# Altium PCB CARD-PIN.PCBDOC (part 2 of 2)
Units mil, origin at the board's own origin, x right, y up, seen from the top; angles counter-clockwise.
Board outline 5110 x 4320 mil, 2 copper layers (Top Layer, Bottom Layer); 210 components, 32 nets, 795 pads, 360 vias.
Unrouted connection lines stored in the file: 450.
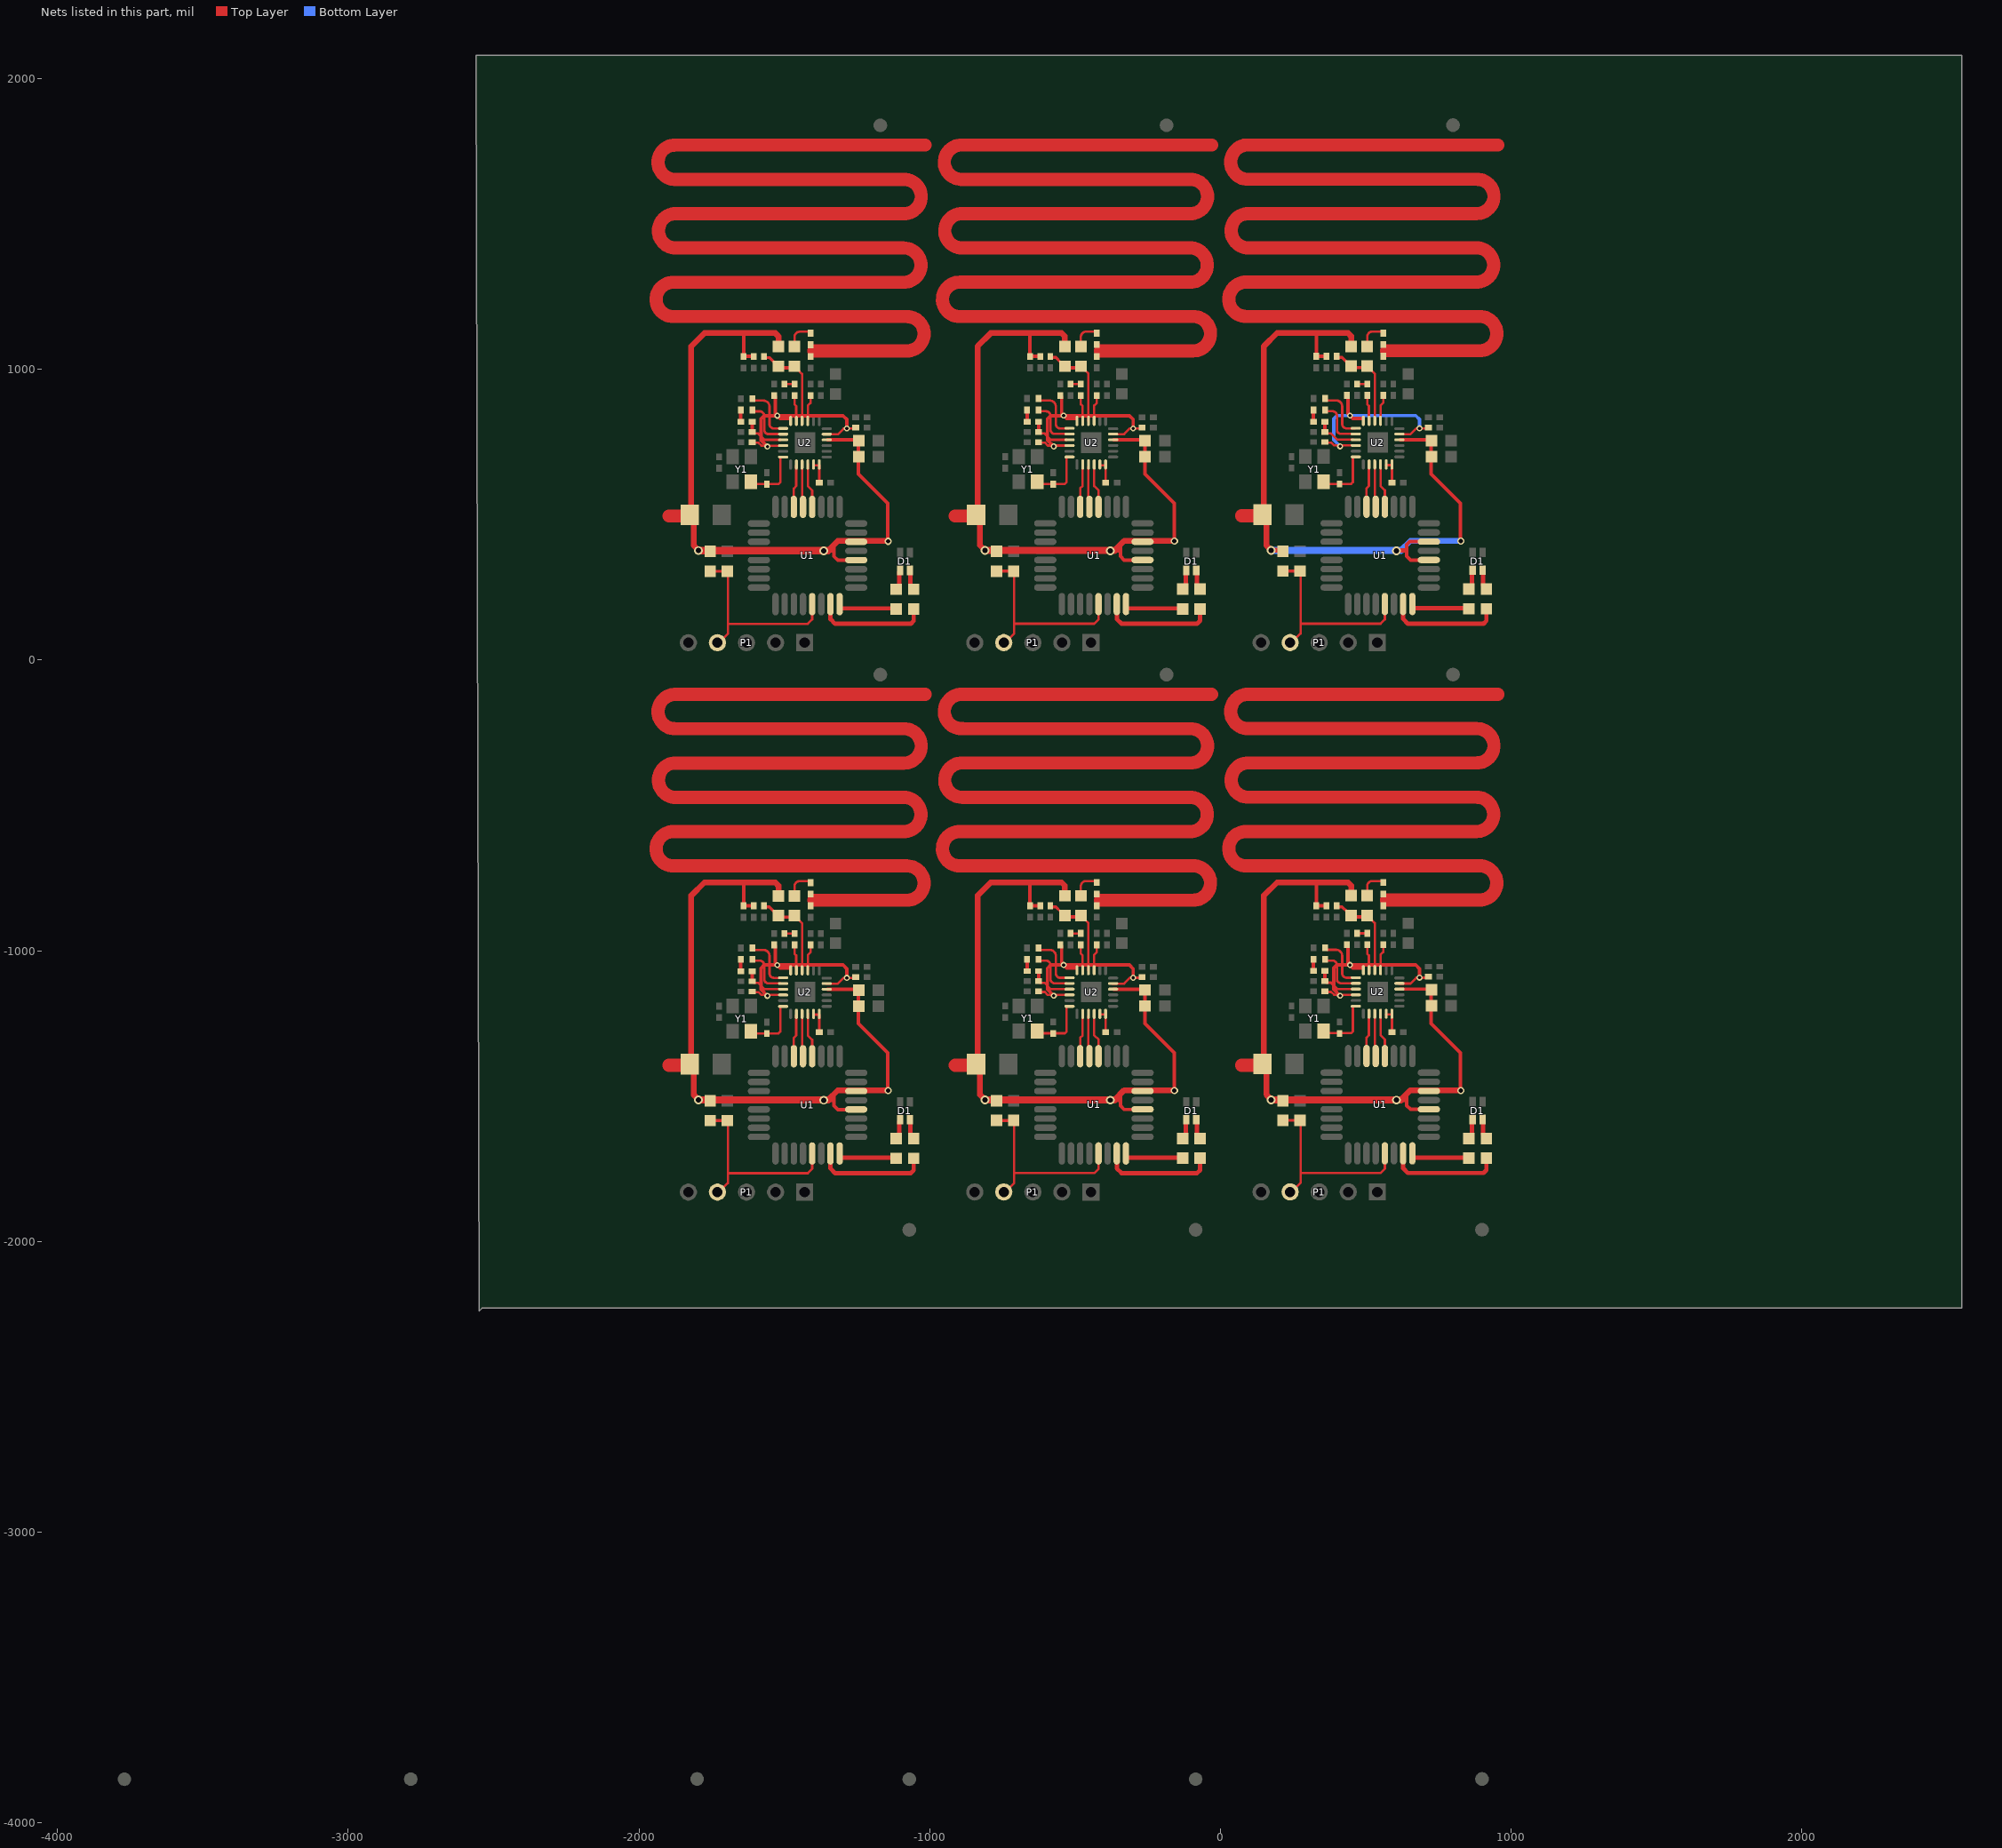
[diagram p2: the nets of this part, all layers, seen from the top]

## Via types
v1: diameter 28, hole 15, Top Layer to Bottom Layer, 240 vias
v2: diameter 20, hole 12, Top Layer to Bottom Layer, 36 vias
v3: diameter 20, hole 10, Top Layer to Bottom Layer, tented top, 30 vias
v4: diameter 22, hole 13, Top Layer to Bottom Layer, 18 vias
v5: diameter 21, hole 11, Top Layer to Bottom Layer, 18 vias
v6: diameter 30, hole 18, Top Layer to Bottom Layer, 12 vias
v7: diameter 25, hole 15, Top Layer to Bottom Layer, 6 vias

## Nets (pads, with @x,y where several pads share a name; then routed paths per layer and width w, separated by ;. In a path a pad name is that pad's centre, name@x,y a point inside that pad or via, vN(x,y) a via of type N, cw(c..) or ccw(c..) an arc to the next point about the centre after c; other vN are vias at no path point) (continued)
NetC9_2: C9.2 C12.2 | length 37793.3
  Top Layer w8: C12.2@-1411,-808.47 -1410,-808.27 C12.2@-1409.38,-808.14 ; C12.2@-1411,1081.53 -1410,1081.73 C12.2@-1409.38,1081.86 ; C12.2@-426,-808.24 -425,-808.03 C12.2@-424.38,-807.9 ; C12.2@-426,1081.76 -425,1081.97 C12.2@-424.38,1082.1 ; C12.2@559,-808 560,-807.79 C12.2@560.62,-807.66 ; C12.2@559,1082 560,1082.21 C12.2@560.62,1082.34
  Top Layer w13: C9.2@-1409.38,-845.45 C12.2@-1409.38,-808.14 ; C9.2@-1409.38,1044.55 C12.2@-1409.38,1081.86 ; C12.2@-1407.73,-805.46 C12.2@-1407.33,-802.49 ; C12.2@-1407.73,1084.54 C12.2@-1407.33,1087.51 ; C9.2@-424.38,-845.22 C12.2@-424.38,-807.9 ; C9.2@-424.38,1044.78 C12.2@-424.38,1082.1 ; C12.2@-422.73,-805.22 C12.2@-422.33,-802.25 ; C12.2@-422.73,1084.78 C12.2@-422.33,1087.75 ; C9.2@560.62,-844.98 C12.2@560.62,-807.66 ; C9.2@560.62,1045.02 C12.2@560.62,1082.34 ; C12.2@562.27,-804.99 C12.2@562.67,-802.02 ; C12.2@562.27,1085.01 C12.2@562.67,1087.98
  Top Layer w45.28: -1879.49,-708.49 -1080.51,-708.49 cw(c-1078.03,-767.49) -1081,-826.47 -1398,-826.47 ; -1879.49,-708.46 cw(c-1881.97,-649.45) -1879,-590.47 -1090.41,-590.47 ; -1879.49,1181.51 -1080.51,1181.51 cw(c-1078.03,1122.51) -1081,1063.53 -1398,1063.53 ; -1879.49,1181.54 cw(c-1881.97,1240.55) -1879,1299.53 -1090.41,1299.53 ; -1876,-236.52 -1090.52,-236.52 cw(c-1088.04,-295.53) -1091.01,-354.51 -1871,-354.51 ccw(c-1873.97,-413.49) -1871.49,-472.49 -1091.51,-472.49 cw(c-1089.03,-531.49) -1092,-590.47 ; -1876,-118.54 -1015,-118.54 ; -1876,1653.48 -1090.52,1653.48 cw(c-1088.04,1594.47) -1091.01,1535.49 -1871,1535.49 ccw(c-1873.97,1476.51) -1871.49,1417.51 -1091.51,1417.51 cw(c-1089.03,1358.51) -1092,1299.53 ; -1876,1771.46 -1015,1771.46 ; -1873,-236.47 cw(c-1875.48,-177.47) -1872.51,-118.49 ; -1873,1653.53 cw(c-1875.48,1712.53) -1872.51,1771.51 ; -894.49,-708.25 -95.51,-708.25 cw(c-93.03,-767.26) -96,-826.24 -413,-826.24 ; -894.49,-708.22 cw(c-896.97,-649.22) -894,-590.24 -105.41,-590.24 ; -894.49,1181.75 -95.51,1181.75 cw(c-93.03,1122.74) -96,1063.76 -413,1063.76 ; -894.49,1181.78 cw(c-896.97,1240.78) -894,1299.76 -105.41,1299.76 ; -891,-236.29 -105.52,-236.29 cw(c-103.04,-295.29) -106.01,-354.27 -886,-354.27 ccw(c-888.97,-413.25) -886.49,-472.25 -106.51,-472.25 cw(c-104.03,-531.26) -107,-590.24 ; -891,-118.3 -30,-118.3 ; -891,1653.71 -105.52,1653.71 cw(c-103.04,1594.71) -106.01,1535.73 -886,1535.73 ccw(c-888.97,1476.75) -886.49,1417.75 -106.51,1417.75 cw(c-104.03,1358.74) -107,1299.76 ; -891,1771.7 -30,1771.7 ; -888,-236.24 cw(c-890.48,-177.23) -887.51,-118.25 ; -888,1653.76 cw(c-890.48,1712.77) -887.51,1771.75 ; 94,-236.05 879.48,-236.05 cw(c881.96,-295.05) 878.99,-354.03 99,-354.03 ccw(c96.03,-413.01) 98.51,-472.02 878.49,-472.02 cw(c880.97,-531.02) 878,-590 ; 94,-118.07 955,-118.07 ; 94,1653.95 879.48,1653.95 cw(c881.96,1594.95) 878.99,1535.97 99,1535.97 ccw(c96.03,1476.99) 98.51,1417.98 878.49,1417.98 cw(c880.97,1358.98) 878,1300 ; 94,1771.93 955,1771.93 ; 97,-236 cw(c94.52,-177) 97.49,-118.02 ; 97,1654 cw(c94.52,1713) 97.49,1771.98 ; 572,-826 889,-826 ccw(c891.97,-767.02) 889.49,-708.02 90.51,-708.02 cw(c88.03,-648.98) 91,-590 879.59,-590 ; 572,1064 889,1064 ccw(c891.97,1122.98) 889.49,1181.98 90.51,1181.98 cw(c88.03,1241.02) 91,1300 879.59,1300
NetC10_1: C10.1 U2.3 | length 531.3
  Top Layer w8: U2.3@-1419.16,-1064.91 -1419.16,-1014.63 -1410,-1005.47 C10.1@-1410,-980.16 ; U2.3@-1419.16,825.09 -1419.16,875.37 -1410,884.53 C10.1@-1410,909.84 ; U2.3@-434.16,-1064.68 -434.16,-1014.39 -425,-1005.24 C10.1@-425,-979.92 ; U2.3@-434.16,825.32 -434.16,875.61 -425,884.76 C10.1@-425,910.08 ; U2.3@550.84,-1064.44 550.84,-1014.16 560,-1005 C10.1@560,-979.68 ; U2.3@550.84,825.56 550.84,875.84 560,885 C10.1@560,910.32
NetC11_2: C11.2 L2.1 L3.1 U2.4 | length 1708.5
  Top Layer w8: L2.1@-1455,-889.47 -1439,-905.47 U2.4@-1439,-1061.47 ; L2.1@-1455,1000.53 -1439,984.53 U2.4@-1439,828.53 ; U2.4@-1439,-1067.47 -1438.99,-1064.91 U2.4@-1439,-1066.47 ; U2.4@-1439,822.53 -1438.99,825.09 U2.4@-1439,823.53 ; L2.1@-470,-889.24 -454,-905.24 U2.4@-454,-1061.24 ; L2.1@-470,1000.76 -454,984.76 U2.4@-454,828.76 ; U2.4@-454,-1067.24 -453.99,-1064.68 U2.4@-454,-1066.24 ; U2.4@-454,822.76 -453.99,825.32 U2.4@-454,823.76 ; L2.1@515,-889 531,-905 U2.4@531,-1061 ; L2.1@515,1001 531,985 U2.4@531,829 ; U2.4@531,-1067 531.01,-1064.44 U2.4@531,-1066 ; U2.4@531,823 531.01,825.56 U2.4@531,824
  Top Layer w10: C11.2@-1567,-849.47 -1551,-849.47 L3.1@-1533.31,-867.16 ; C11.2@-1567,1040.53 -1551,1040.53 L3.1@-1533.31,1022.84 ; C11.2@-582,-849.24 -566,-849.24 L3.1@-548.31,-866.92 ; C11.2@-582,1040.76 -566,1040.76 L3.1@-548.31,1023.08 ; C11.2@403,-849 419,-849 L3.1@436.69,-866.69 ; C11.2@403,1041 419,1041 L3.1@436.69,1023.31
  Top Layer w12: L3.1@-1529,-884.47 L2.1@-1468,-884.47 ; L3.1@-1529,1005.53 L2.1@-1468,1005.53 ; L3.1@-544,-884.24 L2.1@-483,-884.24 ; L3.1@-544,1005.76 L2.1@-483,1005.76 ; L3.1@441,-884 L2.1@502,-884 ; L3.1@441,1006 L2.1@502,1006
NetC12_1: C12.1 L2.2 | length 560.2
  Top Layer w8: L2.2@-1465,-814.47 -1465,-778.54 cw(c-1447.93,-778.54) -1460,-766.47 ; L2.2@-1465,1075.53 -1465,1111.46 cw(c-1447.93,1111.46) -1460,1123.53 ; -1459,-765.47 cw(c-1447.51,-776.96) -1447.51,-760.71 C12.1@-1416.24,-760.71 ; -1459,1124.53 cw(c-1447.51,1113.04) -1447.51,1129.28 C12.1@-1416.24,1129.28 ; L2.2@-480,-814.24 -480,-778.31 cw(c-462.93,-778.31) -475,-766.24 ; L2.2@-480,1075.76 -480,1111.69 cw(c-462.93,1111.69) -475,1123.76 ; -474,-765.24 cw(c-462.51,-776.72) -462.51,-760.48 C12.1@-431.24,-760.48 ; -474,1124.76 cw(c-462.51,1113.28) -462.51,1129.52 C12.1@-431.24,1129.52 ; L2.2@505,-814 505,-778.07 cw(c522.07,-778.07) 510,-766 ; L2.2@505,1076 505,1111.93 cw(c522.07,1111.93) 510,1124 ; 511,-765 cw(c522.49,-776.49) 522.49,-760.24 C12.1@553.76,-760.24 ; 511,1125 cw(c522.49,1113.51) 522.49,1129.76 C12.1@553.76,1129.76
NetC13_1: C13.1 U2.17 U2.18 | length 438.1
  Top Layer w8: U2.17@-1399.47,-1220.03 -1379.79,-1220.03 C13.1@-1379.79,-1273.37 ; U2.17@-1399.47,669.97 -1379.79,669.97 C13.1@-1379.79,616.63 ; U2.17@-414.47,-1219.8 -394.79,-1219.8 C13.1@-394.79,-1273.13 ; U2.17@-414.47,670.2 -394.79,670.2 C13.1@-394.79,616.87 ; U2.17@570.53,-1219.56 590.21,-1219.56 C13.1@590.21,-1272.9 ; U2.17@570.53,670.44 590.21,670.44 C13.1@590.21,617.1
NetC16_2: C16.2 R2.2 | length 172.2
  Top Layer w8: C16.2@-1494.69,-940.79 R2.2@-1466,-940.79 ; C16.2@-1494.69,949.21 R2.2@-1466,949.21 ; C16.2@-509.69,-940.55 R2.2@-481,-940.55 ; C16.2@-509.69,949.45 R2.2@-481,949.45 ; C16.2@475.31,-940.31 R2.2@504,-940.31 ; C16.2@475.31,949.69 R2.2@504,949.69
NetC19_2: C19.2 R4.2 U2.9 | length 777
  Top Layer w8: C19.2@-1610,-1105.47 -1605,-1110.47 -1590,-1110.47 -1568,-1132.47 U2.9@-1514,-1132.47 ; C19.2@-1610,784.53 -1605,779.53 -1590,779.53 -1568,757.53 U2.9@-1514,757.53 ; C19.2@-625,-1105.24 -620,-1110.24 -605,-1110.24 -583,-1132.24 U2.9@-529,-1132.24 ; C19.2@-625,784.76 -620,779.76 -605,779.76 -583,757.76 U2.9@-529,757.76 ; C19.2@360,-1105 365,-1110 380,-1110 402,-1132 U2.9@456,-1132 ; C19.2@360,785 365,780 380,780 402,758 U2.9@456,758
  Top Layer w12: C19.2@-1610,-1097.79 R4.2@-1610,-1075.47 ; C19.2@-1610,792.21 R4.2@-1610,814.53 ; C19.2@-625,-1097.55 R4.2@-625,-1075.24 ; C19.2@-625,792.45 R4.2@-625,814.76 ; C19.2@360,-1097.31 R4.2@360,-1075 ; C19.2@360,792.69 R4.2@360,815
NetC20_2: C20.2 R4.1 | length 258
  Top Layer w12: R4.1@-1650,-1073.47 C20.2@-1650,-1030.47 ; R4.1@-1650,816.53 C20.2@-1650,859.53 ; R4.1@-665,-1073.24 C20.2@-665,-1030.24 ; R4.1@-665,816.76 C20.2@-665,859.76 ; R4.1@320,-1073 C20.2@320,-1030 ; R4.1@320,817 C20.2@320,860
NetC21_2: C21.2 U2.12 Y1.3 | length 1081.6
  Top Layer w8: Y1.3@-1605,-1284.47 -1520,-1284.47 -1514,-1278.47 U2.12@-1514,-1191.68 ; Y1.3@-1605,605.53 -1520,605.53 -1514,611.53 U2.12@-1514,698.32 ; Y1.3@-620,-1284.24 -535,-1284.24 -529,-1278.24 U2.12@-529,-1191.45 ; Y1.3@-620,605.76 -535,605.76 -529,611.76 U2.12@-529,698.55 ; Y1.3@365,-1284 450,-1284 456,-1278 U2.12@456,-1191.21 ; Y1.3@365,606 450,606 456,612 U2.12@456,698.79
NetD1_1: D1.1 R3.2 | length 312.1
  Top Layer w15: R3.2@-1103.99,-1637.46 D1.1@-1104,-1587.47 ; R3.2@-1103.99,252.54 D1.1@-1104,302.53 ; D1.1@-1103,-1579.47 D1.1@-1102.92,-1581.51 ; D1.1@-1103,310.53 D1.1@-1102.92,308.49 ; R3.2@-118.98,-1637.22 D1.1@-119,-1587.24 ; R3.2@-118.98,252.78 D1.1@-119,302.76 ; D1.1@-118,-1579.24 D1.1@-117.92,-1581.27 ; D1.1@-118,310.76 D1.1@-117.92,308.73 ; R3.2@866.02,-1636.99 D1.1@866,-1587 ; R3.2@866.02,253.01 D1.1@866,303 ; D1.1@867,-1579 D1.1@867.08,-1581.04 ; D1.1@867,311 D1.1@867.08,308.96
NetD1_2: D1.2 R5.2 | length 299.9
  Top Layer w15: R5.2@-1065.98,-1632.46 D1.2@-1066,-1582.47 ; R5.2@-1065.98,257.54 D1.2@-1066,307.53 ; R5.2@-80.98,-1632.22 D1.2@-81,-1582.24 ; R5.2@-80.98,257.78 D1.2@-81,307.76 ; R5.2@904.02,-1631.99 D1.2@904,-1582 ; R5.2@904.02,258.01 D1.2@904,308
NetL4_1: L4.1 U2.7 | length 1059.3
  Top Layer w8: L4.1@-1602,-997.47 -1571,-997.47 ; L4.1@-1602,892.53 -1571,892.53 ; -1572,-997.47 cw(c-1572,-1018.47) -1551,-1018.47 ; -1572,892.53 cw(c-1572,871.53) -1551,871.53 ; -1551,-1017.47 -1551,-1078.47 ccw(c-1536,-1078.47) -1536,-1093.47 U2.7@-1508,-1093.47 ; -1551,872.53 -1551,811.53 ccw(c-1536,811.53) -1536,796.53 U2.7@-1508,796.53 ; L4.1@-617,-997.24 -586,-997.24 ; L4.1@-617,892.76 -586,892.76 ; -587,-997.24 cw(c-587,-1018.24) -566,-1018.24 ; -587,892.76 cw(c-587,871.76) -566,871.76 ; -566,-1017.24 -566,-1078.24 ccw(c-551,-1078.24) -551,-1093.24 U2.7@-523,-1093.24 ; -566,872.76 -566,811.76 ccw(c-551,811.76) -551,796.76 U2.7@-523,796.76 ; L4.1@368,-997 399,-997 ; L4.1@368,893 399,893 ; 398,-997 cw(c398,-1018) 419,-1018 ; 398,893 cw(c398,872) 419,872 ; 419,-1017 419,-1078 ccw(c434,-1078) 434,-1093 U2.7@462,-1093 ; 419,873 419,812 ccw(c434,812) 434,797 U2.7@462,797
NetL4_2: L4.2 U2.8 | length 966.7
  Top Layer w8: L4.2@-1609,-1034.47 -1585,-1034.47 cw(c-1585,-1050.47) -1569,-1050.47 -1569,-1098.47 ccw(c-1555,-1098.47) -1555,-1112.47 ; L4.2@-1609,855.53 -1585,855.53 cw(c-1585,839.53) -1569,839.53 -1569,791.53 ccw(c-1555,791.53) -1555,777.53 ; -1556,-1112.47 U2.8@-1514,-1112.47 ; -1556,777.53 U2.8@-1514,777.53 ; L4.2@-624,-1034.24 -600,-1034.24 cw(c-600,-1050.24) -584,-1050.24 -584,-1098.24 ccw(c-570,-1098.24) -570,-1112.24 ; L4.2@-624,855.76 -600,855.76 cw(c-600,839.76) -584,839.76 -584,791.76 ccw(c-570,791.76) -570,777.76 ; -571,-1112.24 U2.8@-529,-1112.24 ; -571,777.76 U2.8@-529,777.76 ; L4.2@361,-1034 385,-1034 cw(c385,-1050) 401,-1050 401,-1098 ccw(c415,-1098) 415,-1112 ; L4.2@361,856 385,856 cw(c385,840) 401,840 401,792 ccw(c415,792) 415,778 ; 414,-1112 U2.8@456,-1112 ; 414,778 U2.8@456,778
NetR2_1: R2.1 U2.5 | length 470.9
  Top Layer w8: R2.1@-1465,-983.47 -1465,-1010.47 -1459,-1016.47 U2.5@-1459,-1059.47 ; R2.1@-1465,906.53 -1465,879.53 -1459,873.53 U2.5@-1459,830.53 ; R2.1@-480,-983.24 -480,-1010.24 -474,-1016.24 U2.5@-474,-1059.24 ; R2.1@-480,906.76 -480,879.76 -474,873.76 U2.5@-474,830.76 ; R2.1@505,-983 505,-1010 511,-1016 U2.5@511,-1059 ; R2.1@505,907 505,880 511,874 U2.5@511,831
NetR3_1: R3.1 U1.32 | length 1171.9
  Top Layer w15: U1.32@-1309.99,-1697.8 U1.32@-1310,-1695.47 ; U1.32@-1309.99,192.2 U1.32@-1310,194.53 ; U1.32@-1306,-1712.47 R3.1@-1113,-1712.47 ; U1.32@-1306,177.53 R3.1@-1113,177.53 ; U1.32@-324.99,-1697.56 U1.32@-325,-1695.24 ; U1.32@-324.99,192.44 U1.32@-325,194.76 ; U1.32@-321,-1712.24 R3.1@-128,-1712.24 ; U1.32@-321,177.76 R3.1@-128,177.76 ; U1.32@660.01,-1697.32 U1.32@660,-1695 ; U1.32@660.01,192.68 U1.32@660,195 ; U1.32@664,-1712 R3.1@857,-1712 ; U1.32@664,178 R3.1@857,178
NetR5_1: R5.1 U1.31 | length 2379.4
  Top Layer w15: U1.31@-1341,-1693.47 -1341.02,-1697.8 -1341.01,-1749.47 -1325,-1765.47 -1064.92,-1765.39 -1055,-1755.47 R5.1@-1055,-1714.47 R5.1@-1053,-1712.47 ; U1.31@-1341,196.53 -1341.02,192.2 -1341.01,140.53 -1325,124.53 -1064.92,124.61 -1055,134.53 R5.1@-1055,175.53 R5.1@-1053,177.53 ; U1.31@-356,-1693.24 -356.02,-1697.56 -356.01,-1749.23 -340,-1765.24 -79.92,-1765.16 -70,-1755.23 -70.01,-1714.25 R5.1@-68,-1712.24 ; U1.31@-356,196.76 -356.02,192.44 -356.01,140.77 -340,124.76 -79.92,124.84 -70,134.77 -70.01,175.75 R5.1@-68,177.76 ; U1.31@629,-1693 628.98,-1697.32 628.99,-1749 645,-1765 905.08,-1764.92 915,-1755 R5.1@915,-1714 R5.1@917,-1712 ; U1.31@629,197 628.98,192.68 628.99,141 645,125 905.08,125.08 915,135 R5.1@915,176 R5.1@917,178
RST: C4.1 P1.4 R1.1 U1.29 | length 3882.7
  Top Layer w8: P1.4@-1730,-1835.47 -1694,-1799.47 C4.1@-1694,-1584.47 ; P1.4@-1730,54.53 -1694,90.53 C4.1@-1694,305.53 ; -1692,-1765.47 -1419,-1765.47 -1404,-1750.47 U1.29@-1404,-1722.47 ; -1692,124.53 -1419,124.53 -1404,139.53 U1.29@-1404,167.53 ; P1.4@-745,-1835.24 -709,-1799.24 C4.1@-709,-1584.24 ; P1.4@-745,54.76 -709,90.76 C4.1@-709,305.76 ; -707,-1765.24 -434,-1765.24 -419,-1750.24 U1.29@-419,-1722.24 ; -707,124.76 -434,124.76 -419,139.76 U1.29@-419,167.76 ; P1.4@240,-1835 276,-1799 C4.1@276,-1584 ; P1.4@240,55 276,91 C4.1@276,306 ; 278,-1765 551,-1765 566,-1750 U1.29@566,-1722 ; 278,125 551,125 566,140 U1.29@566,168
  Top Layer w10: R1.1@-1755,-1584.47 C4.1@-1696,-1584.47 ; R1.1@-1755,305.53 C4.1@-1696,305.53 ; R1.1@-770,-1584.24 C4.1@-711,-1584.24 ; R1.1@-770,305.76 C4.1@-711,305.76 ; R1.1@215,-1584 C4.1@274,-1584 ; R1.1@215,306 C4.1@274,306
SCK: U1.13 U2.15 | length 690
  Top Layer w8: U1.13@-1439,-1341.47 U2.15@-1439,-1226.47 ; U1.13@-1439,548.53 U2.15@-1439,663.53 ; U1.13@-454,-1341.24 U2.15@-454,-1226.24 ; U1.13@-454,548.76 U2.15@-454,663.76 ; U1.13@531,-1341 U2.15@531,-1226 ; U1.13@531,549 U2.15@531,664
SCS: U1.14 U2.14 | length 870.6
  Top Layer w8: U1.14@-1467.24,-1363.15 -1467.24,-1299.72 -1459,-1291.47 U2.14@-1459,-1221.47 ; U1.14@-1467.24,526.85 -1467.24,590.28 -1459,598.53 U2.14@-1459,668.53 ; U1.14@-482.24,-1362.91 -482.24,-1299.48 -474,-1291.24 U2.14@-474,-1221.24 ; U1.14@-482.24,527.09 -482.24,590.52 -474,598.76 U2.14@-474,668.76 ; U1.14@502.76,-1362.68 502.76,-1299.24 511,-1291 U2.14@511,-1221 ; U1.14@502.76,527.32 502.76,590.76 511,599 U2.14@511,669
SDIO: U1.12 U2.16 | length 850.6
  Top Layer w8: U2.16@-1419,-1220.03 U2.16@-1419,-1219.47 ; U2.16@-1419,-1216.47 -1419,-1291.47 -1404,-1306.47 U1.12@-1404,-1351.47 ; U2.16@-1419,669.97 U2.16@-1419,670.53 ; U2.16@-1419,673.53 -1419,598.53 -1404,583.53 U1.12@-1404,538.53 ; U2.16@-434,-1219.8 U2.16@-434,-1219.24 ; U2.16@-434,-1216.24 -434,-1291.24 -419,-1306.24 U1.12@-419,-1351.24 ; U2.16@-434,670.2 U2.16@-434,670.76 ; U2.16@-434,673.76 -434,598.76 -419,583.76 U1.12@-419,538.76 ; U2.16@551,-1219.56 U2.16@551,-1219 ; U2.16@551,-1216 551,-1291 566,-1306 U1.12@566,-1351 ; U2.16@551,670.44 U2.16@551,671 ; U2.16@551,674 551,599 566,584 U1.12@566,539
VCC: C1.2 C5.1 C6.1 C14.1 C15.1 L3.2 R1.2 U1.4 U1.6 U2.22 | length 15657.4
  Top Layer w12: C15.1@-1641,-846.47 -1640,-845.47 -1640,-765.47 ; C15.1@-1641,-845.47 C14.1@-1603,-845.47 ; C15.1@-1641,1043.53 -1640,1044.53 -1640,1124.53 ; C15.1@-1641,1044.53 C14.1@-1603,1044.53 ; U2.22@-1351.44,-1132.63 C6.1@-1244,-1132.63 ; U2.22@-1351.44,757.37 C6.1@-1244,757.37 ; U1.4@-1272,-1546.47 -1316,-1546.47 -1329,-1533.47 -1329,-1493.47 -1318,-1482.47 U1.6@-1271,-1482.47 ; U1.4@-1272,343.53 -1316,343.53 -1329,356.53 -1329,396.53 -1318,407.53 U1.6@-1271,407.53 ; C6.1@-1245,-1135.47 -1245,-1250.47 -1144,-1351.47 v7@-1144,-1480.47 ; C6.1@-1245,754.53 -1245,639.53 -1144,538.53 v7@-1144,409.53 ; C15.1@-656,-846.24 -655,-845.24 -655,-765.24 ; C15.1@-656,-845.24 C14.1@-618,-845.24 ; C15.1@-656,1043.76 -655,1044.76 -655,1124.76 ; C15.1@-656,1044.76 C14.1@-618,1044.76 ; U2.22@-366.44,-1132.39 C6.1@-259,-1132.39 ; U2.22@-366.44,757.61 C6.1@-259,757.61 ; U1.4@-287,-1546.24 -331,-1546.24 -344,-1533.24 -344,-1493.24 -333,-1482.24 U1.6@-286,-1482.24 ; U1.4@-287,343.76 -331,343.76 -344,356.76 -344,396.76 -333,407.76 U1.6@-286,407.76 ; C6.1@-260,-1135.24 -260,-1250.24 -159,-1351.24 v7@-159,-1480.24 ; C6.1@-260,754.76 -260,639.76 -159,538.76 v7@-159,409.76 ; C15.1@329,-846 330,-845 330,-765 ; C15.1@329,-845 C14.1@367,-845 ; C15.1@329,1044 330,1045 330,1125 ; C15.1@329,1045 C14.1@367,1045 ; U2.22@618.56,-1132.16 C6.1@726,-1132.16 ; U2.22@618.56,757.84 C6.1@726,757.84 ; U1.4@698,-1546 654,-1546 641,-1533 641,-1493 652,-1482 U1.6@699,-1482 ; U1.4@698,344 654,344 641,357 641,397 652,408 U1.6@699,408 ; C6.1@725,-1135 725,-1250 826,-1351 v7@826,-1480 ; C6.1@725,755 725,640 826,539 v7@826,410
  Top Layer w15: v6@-1363,-1513.47 -1332,-1513.47 ; v6@-1363,376.53 -1332,376.53 ; v6@-378,-1513.24 -347,-1513.24 ; v6@-378,376.76 -347,376.76 ; v6@607,-1513 638,-1513 ; v6@607,377 638,377
  Top Layer w16: v6@-1795,-1512.47 R1.2@-1759,-1512.47 ; v6@-1795,377.53 R1.2@-1759,377.53 ; v6@-810,-1512.24 R1.2@-774,-1512.24 ; v6@-810,377.76 R1.2@-774,377.76 ; v6@175,-1512 R1.2@211,-1512 ; v6@175,378 R1.2@211,378
  Top Layer w20: C1.2@-1820,-1380.47 -1820,-810.47 -1775,-765.47 -1531,-765.47 -1520,-776.47 L3.2@-1520,-811.47 ; C1.2@-1820,509.53 -1820,1079.53 -1775,1124.53 -1531,1124.53 -1520,1113.53 L3.2@-1520,1078.53 ; C1.2@-1812,-1396.47 -1812,-1495.47 v6@-1795,-1512.47 ; C1.2@-1812,493.53 -1812,394.53 v6@-1795,377.53 ; -1349,-1513.47 -1316,-1480.47 v7@-1143,-1480.47 ; -1349,376.53 -1316,409.53 v7@-1143,409.53 ; C1.2@-835,-1380.24 -835,-810.24 -790,-765.24 -546,-765.24 -535,-776.24 L3.2@-535,-811.24 ; C1.2@-835,509.76 -835,1079.76 -790,1124.76 -546,1124.76 -535,1113.76 L3.2@-535,1078.76 ; C1.2@-827,-1396.24 -827,-1495.24 v6@-810,-1512.24 ; C1.2@-827,493.76 -827,394.76 v6@-810,377.76 ; -364,-1513.24 -331,-1480.24 v7@-158,-1480.24 ; -364,376.76 -331,409.76 v7@-158,409.76 ; C1.2@150,-1380 150,-810 195,-765 439,-765 450,-776 L3.2@450,-811 ; C1.2@150,510 150,1080 195,1125 439,1125 450,1114 L3.2@450,1079 ; C1.2@158,-1396 158,-1495 v6@175,-1512 ; C1.2@158,494 158,395 v6@175,378 ; 621,-1513 654,-1480 v7@827,-1480
  Top Layer w25: v6@-1794,-1513.47 -1349,-1513.47 ; v6@-1794,376.53 -1349,376.53 ; v6@-809,-1513.24 -364,-1513.24 ; v6@-809,376.76 -364,376.76 ; v6@176,-1513 621,-1513
  Top Layer w45: -1897,-1394.47 C1.2@-1849,-1394.47 ; -1897,495.53 C1.2@-1849,495.53 ; -912,-1394.24 C1.2@-864,-1394.24 ; -912,495.76 C1.2@-864,495.76 ; 73,-1394 C1.2@121,-1394 ; 73,496 C1.2@121,496
  Bottom Layer w20: 621,377 654,410 v7@827,410
  Bottom Layer w25: v6@176,377 621,377
  other v6: -1364,-1514.47 -379,-1514.24 606,-1514 -1795,-1513.47 -810,-1513.24 175,-1513 -1364,375.53 -379,375.76 606,376 -1795,376.53 -810,376.76 175,377
  other v7: -1143,-1481.47 -158,-1481.24 827,-1481 -1143,408.53 -158,408.76 827,409
VDA: C3.1 C17.1 C18.2 U2.6 U2.10 U2.23 | length 4613
  Top Layer w8: C18.2@-1604,-1142.47 -1589,-1142.47 -1579,-1152.47 U2.10@-1499,-1152.47 ; C18.2@-1604,747.53 -1589,747.53 -1579,737.53 U2.10@-1499,737.53 ; U2.23@-1356,-1113.47 -1316,-1113.47 -1296,-1093.47 C3.1@-1260,-1093.47 ; U2.23@-1356,776.53 -1316,776.53 -1296,796.53 C3.1@-1260,796.53 ; C18.2@-619,-1142.24 -604,-1142.24 -594,-1152.24 U2.10@-514,-1152.24 ; C18.2@-619,747.76 -604,747.76 -594,737.76 U2.10@-514,737.76 ; U2.23@-371,-1113.24 -331,-1113.24 -311,-1093.24 C3.1@-275,-1093.24 ; U2.23@-371,776.76 -331,776.76 -311,796.76 C3.1@-275,796.76 ; C18.2@366,-1142 381,-1142 391,-1152 U2.10@471,-1152 ; C18.2@366,748 381,748 391,738 U2.10@471,738 ; U2.23@614,-1113 654,-1113 674,-1093 C3.1@710,-1093 ; U2.23@614,777 654,777 674,797 C3.1@710,797
  Top Layer w12: v5(-1558,-1155.47) -1580,-1133.47 -1580,-1060.47 -1569,-1049.47 -1298,-1049.47 -1285,-1062.47 v5(-1285,-1093.47) ; v5(-1558,734.53) -1580,756.53 -1580,829.53 -1569,840.53 -1298,840.53 -1285,827.53 v5(-1285,796.53) ; C17.1@-1531,-984.16 -1531,-1042.47 -1514,-1059.47 U2.6@-1481,-1059.47 ; C17.1@-1531,905.84 -1531,847.53 -1514,830.53 U2.6@-1481,830.53 ; v5(-573,-1155.24) -595,-1133.24 -595,-1060.24 -584,-1049.24 -313,-1049.24 -300,-1062.24 v5(-300,-1093.24) ; v5(-573,734.76) -595,756.76 -595,829.76 -584,840.76 -313,840.76 -300,827.76 v5(-300,796.76) ; C17.1@-546,-983.92 -546,-1042.24 -529,-1059.24 U2.6@-496,-1059.24 ; C17.1@-546,906.08 -546,847.76 -529,830.76 U2.6@-496,830.76 ; v5(412,-1155) 390,-1133 390,-1060 401,-1049 672,-1049 685,-1062 v5(685,-1093) ; C17.1@439,-983.68 439,-1042 456,-1059 U2.6@489,-1059 ; C17.1@439,906.32 439,848 456,831 U2.6@489,831
  Bottom Layer w12: v5(412,735) 390,757 390,830 401,841 672,841 685,828 v5(685,797)
  other v5: -1524,-1049.47 -539,-1049.24 446,-1049 -1524,840.53 -539,840.76 446,841
pads on no net: U1.2 U1.7 U1.8 U1.10 U1.11 U1.18 U1.19 U1.20 U1.22 U1.23 U1.24 U1.25 U1.26 U1.27 U1.28 U1.30 U2.21 Y1.2 Y1.4
copper on no net: | length 76094.6
  Top Layer w6: -3940,-3780.71 -3940,-3900.47 -985,-3900.47 -985,-3780.47 ; -2955,-3780.47 -2955,-3900.24 0,-3900.24 0,-3780.24 ; -1970,-3780.24 -1970,-3900 985,-3900 985,-3780 ; -1355,-1015.47 -1355,-920.47 -1360,-920.47 -1560,-920.47 -1560,-1010.47 -1560,-1015.47 -1070,-1015.47 ; -1355,874.53 -1355,969.53 -1360,969.53 -1560,969.53 -1560,879.53 -1560,874.53 -1070,874.53 ; -1075,-80.47 -1030,-80.47 -1030,-0.47 ; -1075,-80 -1075,-0.71 ; -1075,1809.53 -1030,1809.53 -1030,1889.53 -985,1889.53 ; -1075,1810 -1075,1889.29 -1970,1889.29 ; -985,-2010.47 -985,-1890.47 ; -370,-1015.24 -370,-920.24 -375,-920.24 -575,-920.24 -575,-1010.24 -575,-1015.24 -85,-1015.24 ; -370,874.76 -370,969.76 -375,969.76 -575,969.76 -575,879.76 -575,874.76 -85,874.76 ; -90,-80.24 -45,-80.24 -45,-0.24 ; -90,-79.76 -90,-0.47 ; -90,1809.76 -45,1809.76 -45,1889.76 0,1889.76 0,-0.24 ; -90,1810.24 -90,1889.53 -985,1889.53 ; 0,-2010.24 0,-1890.24 ; 615,-1015 615,-920 610,-920 410,-920 410,-1010 410,-1015 900,-1015 ; 895,-80 940,-80 940,0 985,0 985,-1890 ; 895,-79.53 895,-0.24 0,-0.24 ; -1970,-1890.71 -1075,-1890.71 -1970,-1890.71 ; -1970,-1890.71 -1970,-0.71 ; -1970,-1890.71 -1970,-0.71 ; -1970,-0.71 -1075,-0.71 ; -1970,-0.71 -1970,-1890.47 -1075,-1890.47 -1075,-1810.47 -1030,-1810.47 -1030,-1890.47 ; -1970,-0.71 -1075,-0.71 ; -1970,-0.71 -1970,1889.29 ; -1970,-0.71 -1970,1889.29 ; -1970,-0.71 -1075,-0.71 ; -1970,1889.29 -1970,-0.47 -1075,-0.47 -1075,79.53 -1030,79.53 -1030,-0.47 ; -1030,-1890.47 -985,-1890.47 ; -1030,-1890.47 -985,-1890.47 ; -1030,-1890.47 -985,-1890.47 ; -1030,-0.47 -985,-0.47 ; -1030,-0.47 -985,-0.47 ; -1030,-0.47 -985,-0.47 ; -1030,-0.47 -985,-0.47 ; -985,-1890.47 -90,-1890.47 -985,-1890.47 ; -985,-1890.47 -985,-0.47 ; -985,-1890.47 -985,-0.47 ; -985,-1890.47 -985,-0.47 ; -985,-0.47 -90,-0.47 ; -985,-0.47 -985,-1890.24 -90,-1890.24 -90,-1810.24 -45,-1810.24 -45,-1890.24 ; -985,-0.47 -985,1889.53 ; -985,-0.47 -90,-0.47 ; -985,-0.47 -985,1889.53 ; -985,-0.47 -985,1889.53 ; -985,-0.47 -90,-0.47 ; -985,1889.53 -985,-0.24 -90,-0.24 -90,79.76 -45,79.76 -45,-0.24 ; -45,-1890.24 0,-1890.24 ; -45,-1890.24 0,-1890.24 ; -45,-1890.24 0,-1890.24 ; -45,-0.24 0,-0.24 ; -45,-0.24 0,-0.24 ; -45,-0.24 0,-0.24 ; -45,-0.24 0,-0.24 ; 0,-1890.24 895,-1890.24 0,-1890.24 ; 0,-1890.24 0,-0.24 ; 0,-1890.24 0,-0.24 ; 0,-1890.24 0,-0.24 ; 0,-0.24 0,-1890 895,-1890 895,-1810 940,-1810 940,-1890 ; 940,-1890 985,-1890 ; 940,-1890 985,-1890 ; 940,-1890 985,-1890 ; -1250,-1015.47 -1030,-1015.47 -1030,-915.47 -1250,-915.47 -1250,-1015.47 ; -1250,874.53 -1250,974.53 -1030,974.53 -1030,874.53 -1250,874.53 ; -265,-1015.24 -45,-1015.24 -45,-915.24 -265,-915.24 -265,-1015.24 ; -265,874.76 -265,974.76 -45,974.76 -45,874.76 -265,874.76 ; 720,-1015 720,-915 940,-915 940,-1015 720,-1015

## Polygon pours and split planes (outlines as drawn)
GND on Top Layer "Bottom Layer-No Net" (solid, remove dead copper, pour order 1001): -490,210 1255,210 1345,120 1200,-25 1200,-1915 -150,-1915 -210,-1975
GND on Top Layer "Bottom Layer-No Net" (solid, remove dead copper, pour order 1000): -85,95 -75,85 1135,85 1135,-2045 1150,-2060 1145,-2065 -125,-2065
GND on Top Layer "Bottom Layer-No Net" (solid, remove dead copper, pour order 1000): -1070,94.76 -1060,84.76 150,84.76 150,-2045.24 165,-2060.24 160,-2065.24 -1110,-2065.24
GND on Top Layer "Bottom Layer-No Net" (solid, remove dead copper, pour order 1001): -1475,209.76 270,209.76 360,119.76 215,-25.24 215,-1915.24 -1135,-1915.24 -1195,-1975.24
GND on Top Layer "Bottom Layer-No Net" (solid, remove dead copper, pour order 1000): -2055,94.53 -2045,84.53 -835,84.53 -835,-2045.47 -820,-2060.47 -825,-2065.47 -2095,-2065.47
GND on Top Layer "Bottom Layer-No Net" (solid, remove dead copper, pour order 1001): -2460,209.53 -715,209.53 -625,119.53 -770,-25.47 -770,-1915.47 -2120,-1915.47 -2180,-1975.47
GND on Top Layer "Bottom Layer-No Net" (solid, remove dead copper, pour order 1001): -2460,2099.53 -715,2099.53 -625,2009.53 -770,1864.53 -770,-25.47 -2120,-25.47 -2180,-85.47
GND on Top Layer "Bottom Layer-No Net" (solid, remove dead copper, pour order 1000): -2055,1984.53 -2045,1974.53 -835,1974.53 -835,-155.47 -820,-170.47 -825,-175.47 -2095,-175.47
GND on Top Layer "Bottom Layer-No Net" (solid, remove dead copper, pour order 1001): -1475,2099.76 270,2099.76 360,2009.76 215,1864.76 215,-25.24 -1135,-25.24 -1195,-85.24
GND on Top Layer "Bottom Layer-No Net" (solid, remove dead copper, pour order 1000): -1070,1984.76 -1060,1974.76 150,1974.76 150,-155.24 165,-170.24 160,-175.24 -1110,-175.24
GND on Top Layer "Bottom Layer-No Net" (solid, remove dead copper, pour order 1000): -85,1985 -75,1975 1135,1975 1135,-155 1150,-170 1145,-175 -125,-175
GND on Bottom Layer "Bottom Layer-No Net" (solid, remove dead copper, pour order 1001): -490,2100 1255,2100 1345,2010 1200,1865 1200,-25 -150,-25 -210,-85

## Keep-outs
Keep-Out Layer:
  lines w6: -1970,-1890.24 -1970,-2010 985,-2010 985,-1890 ; 895,1810 940,1810 940,1890 985,1890 985,0 ; 895,1810.47 895,1889.76 0,1889.76 ; 0,-0.24 895,-0.24 0,-0.24 ; 0,-0.24 0,1889.76 ; 0,-0.24 0,1889.76 ; 0,1889.76 0,0 895,0 895,80 940,80 940,0 ; 940,0 985,0 ; 940,0 985,0 ; 940,0 985,0

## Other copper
Top Layer:
  rectangle: 10,-995 110,-815
  rectangle: 10,-1475 110,-1305
  rectangle net GND: 475,-1205 600,-1090
  rectangle net GND: 15,-1070 120,-800
  rectangle net GND: 13,-992 105,-820
  rectangle net VCC: 13,-1470 105,-1308
  rectangle net VCC: -972,-1470.24 -880,-1308.24
  rectangle net GND: -972,-992.24 -880,-820.24
  rectangle net GND: -970,-1070.24 -865,-800.24
  rectangle net GND: -510,-1205.24 -385,-1090.24
  rectangle: -975,-1475.24 -875,-1305.24
  rectangle: -975,-995.24 -875,-815.24
  rectangle net VCC: -1957,-1470.47 -1865,-1308.47
  rectangle net GND: -1957,-992.47 -1865,-820.47
  rectangle net GND: -1955,-1070.47 -1850,-800.47
  rectangle net GND: -1495,-1205.47 -1370,-1090.47
  rectangle: -1960,-1475.47 -1860,-1305.47
  rectangle: -1960,-995.47 -1860,-815.47
  rectangle: -1960,894.53 -1860,1074.53
  rectangle: -1960,414.53 -1860,584.53
  rectangle net GND: -1495,684.53 -1370,799.53
  rectangle net GND: -1955,819.53 -1850,1089.53
  rectangle net GND: -1957,897.53 -1865,1069.53
  rectangle net VCC: -1957,419.53 -1865,581.53
  rectangle: -975,894.76 -875,1074.76
  rectangle: -975,414.76 -875,584.76
  rectangle net GND: -510,684.76 -385,799.76
  rectangle net GND: -970,819.76 -865,1089.76
  rectangle net GND: -972,897.76 -880,1069.76
  rectangle net VCC: -972,419.76 -880,581.76
  rectangle net VCC: 13,420 105,582
  rectangle net GND: 13,898 105,1070
  rectangle net GND: 15,820 120,1090
  pour cut-out: 485,-1090 595,-1090 595,-1200 485,-1200
  pour cut-out: -500,-1090.24 -390,-1090.24 -390,-1200.24 -500,-1200.24
  pour cut-out: -1485,-1090.47 -1375,-1090.47 -1375,-1200.47 -1485,-1200.47
  pour cut-out: -1485,799.53 -1375,799.53 -1375,689.53 -1485,689.53
  pour cut-out: -500,799.76 -390,799.76 -390,689.76 -500,689.76
  pour cut-out: 485,800 595,800 595,690 485,690
  text "RFID CARD V1.2" at -1760,1454.53 h60
  text "RFID CARD V1.2" at -775,1454.76 h60
  text "+" at -1930,349.53 h100
  text "+" at -945,349.76 h100
  text "RFID CARD V1.2" at -1760,-435.47 h60
  text "RFID CARD V1.2" at -775,-435.24 h60
  text "RFID CARD V1.2" at 210,-435 h60
  text "+" at -1930,-1540.47 h100
  text "+" at -945,-1540.24 h100
  text "+" at 40,-1540 h100
Bottom Layer:
  rectangle net GND: 475,685 600,800

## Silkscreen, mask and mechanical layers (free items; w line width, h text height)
Top Overlay:
  lines w6: 615,875 615,970 610,970 410,970 410,880 410,875 900,875 ; 720,875 940,875 940,975 720,975 720,875
  text "RFID CARD V1.2" at 210,1455 h60
  text "+" at 40,350 h100
Top Solder:
  rectangle: 10,415 110,585
  rectangle: 10,895 110,1075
